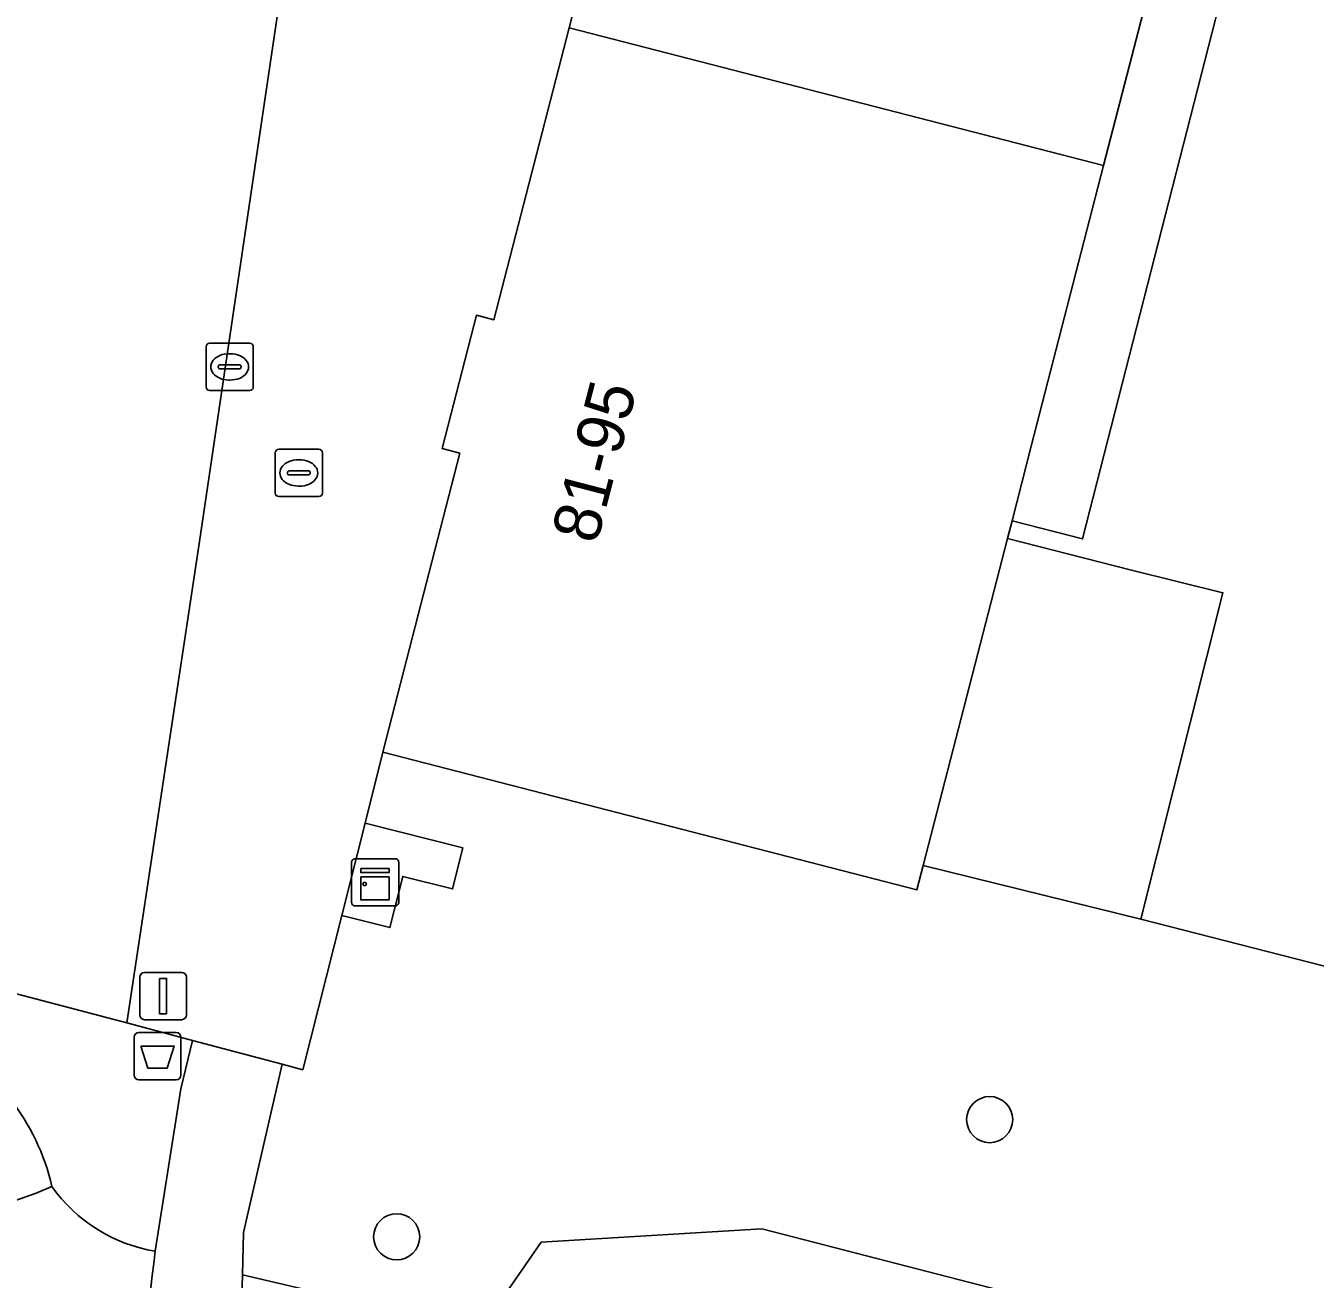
# Model space of a CAD drawing. Extents: x 163683 to 164494, y 382709 to 383872.
# Drawn here: x 164040.92 to 164068.25, y 383122.29 to 383148.85 of the extents above; entities that cross this region are included whole.
import ezdxf

# ---------------------------------------------------------------- set-up
doc = ezdxf.new("R2010")
doc.units = 0
for name, color, linetype in [('IMGEO_Afvalbak', 7, 'Continuous'), ('IMGEO_Boom', 7, 'Continuous'), ('IMGEO_Groenvoorziening', 7, 'Continuous'), ('IMGEO_Kast', 7, 'Continuous'), ('IMGEO_Kolk', 7, 'Continuous'), ('IMGEO_Lichtmast', 7, 'Continuous'), ('IMGEO_Pand', 7, 'Continuous'), ('IMGEO_Pand_nummerreeks', 7, 'Continuous'), ('IMGEO_Rioolput', 7, 'Continuous'), ('IMGEO_Terreindeel_gesloten', 7, 'Continuous'), ('IMGEO_Voetpad_halfverhard', 7, 'Continuous'), ('IMGEO_Voetpad_open', 7, 'Continuous')]:
    doc.layers.add(name, color=color, linetype=linetype)

msp = doc.modelspace()

# ---------------------------------------------------------------- linework, layer by layer
at = {"layer": 'IMGEO_Afvalbak'}
for p, q in [((164043.319, 383127.515), (164044.109, 383127.515)), ((164044.109, 383127.515), (164043.319, 383127.515)), ((164043.219, 383126.615), (164043.219, 383127.415)), ((164043.219, 383127.415), (164043.219, 383126.615)), ((164044.209, 383127.415), (164044.209, 383126.615)), ((164044.209, 383126.615), (164044.209, 383127.415)), ((164044.109, 383126.515), (164043.319, 383126.515)), ((164043.319, 383126.515), (164044.109, 383126.515))]:
    msp.add_line(p, q, dxfattribs=at)
msp.add_lwpolyline([(164043.362, 383127.229), (164044.066, 383127.229), (164043.917, 383126.759), (164043.511, 383126.759), (164043.362, 383127.229)], dxfattribs=at)
for centre, start, end in [((164043.319, 383127.415), 90, 180), ((164043.319, 383127.415), 90, 180), ((164044.109, 383127.415), 0, 90), ((164044.109, 383127.415), 360, 90), ((164043.319, 383126.615), 180, 270), ((164043.319, 383126.615), 180, 270), ((164044.109, 383126.615), 270, 0), ((164044.109, 383126.615), 270, 0)]:
    msp.add_arc(centre, 0.1, start, end, dxfattribs=at)
at = {"layer": 'IMGEO_Boom'}
for centre in [(164061.351, 383125.67), (164048.782, 383123.187)]:
    msp.add_circle(centre, 0.489, dxfattribs=at)
at = {"layer": 'IMGEO_Groenvoorziening'}
for points in [[(164033.039, 383156.561), (164032.775, 383155.553), (164034.669, 383155.046), (164036.178, 383154.914), (164040.121, 383152.198), (164037.77, 383136.602), (164036.683, 383129.392), (164043.063, 383127.721), (164044.6, 383137.924), (164047.39, 383156.736), (164048.093, 383161.745), (164033.321, 383156.926)], [(164043.664, 383122.88), (164044.204, 383126.323), (164044.455, 383127.349), (164043.063, 383127.721), (164036.683, 383129.392), (164026.707, 383132.006), (164026.062, 383132.169), (164024.387, 383128.152), (164023.605, 383126.999)], [(164073.286, 383118.477), (164075.444, 383118.477), (164056.521, 383123.358), (164051.842, 383123.072), (164050.554, 383121.2), (164045.512, 383122.377), (164045.457, 383120.45)]]:
    msp.add_lwpolyline(points, dxfattribs=at)
for points in [[(164090.269, 383148.889), (164070.835, 383153.95), (164070.759, 383160.427), (164070.291, 383160.541), (164069.165, 383160.815), (164067.292, 383153.494), (164063.321, 383137.974), (164061.826, 383138.36), (164061.728, 383137.981), (164064.361, 383137.31), (164066.296, 383136.835), (164064.552, 383129.914), (164086.033, 383124.421)], [(164064.361, 383137.31), (164061.728, 383137.981), (164059.942, 383131.053), (164064.552, 383129.914), (164066.296, 383136.835)], [(164082.061, 383116.77), (164083.693, 383116.349), (164084.602, 383116.796), (164086.033, 383124.421), (164064.552, 383129.914), (164059.942, 383131.053), (164059.809, 383130.537), (164048.491, 383133.455), (164048.111, 383131.953), (164050.186, 383131.429), (164049.966, 383130.557), (164048.91, 383130.825), (164048.636, 383129.74), (164047.617, 383129.998), (164046.79, 383126.726), (164046.355, 383126.842), (164045.537, 383123.279), (164045.512, 383122.377), (164050.554, 383121.2), (164051.842, 383123.072), (164056.521, 383123.358), (164075.444, 383118.477)]]:
    msp.add_lwpolyline(points, close=True, dxfattribs=at)
for centre, radius, start, end in [((164036.803, 383123.163), 4.798, 13.1495, 62.5729), ((164036.803, 383123.163), 4.798, 13.1495, 62.5729), ((164037.987, 383132.129), 8.613, 218.9461, 293.8885), ((164037.987, 383132.129), 8.613, 218.9461, 293.8885), ((164044.217, 383126.192), 3.358, 215.2526, 260.5158), ((164044.217, 383126.192), 3.358, 215.2526, 260.5158), ((164083.855, 383117.788), 40.512, 172.78, 184.5241)]:
    msp.add_arc(centre, radius, start, end, dxfattribs=at)
at = {"layer": 'IMGEO_Kast'}
for p, q in [((164047.826, 383130.274), (164047.826, 383131.115)), ((164047.826, 383131.115), (164047.826, 383130.274)), ((164047.901, 383131.199), (164048.742, 383131.199)), ((164048.742, 383131.199), (164047.901, 383131.199)), ((164048.826, 383131.124), (164048.826, 383130.283)), ((164048.826, 383130.283), (164048.826, 383131.124)), ((164048.751, 383130.199), (164047.91, 383130.199)), ((164047.91, 383130.199), (164048.751, 383130.199))]:
    msp.add_line(p, q, dxfattribs=at)
for points in [[(164048.021, 383130.989), (164048.621, 383130.989), (164048.621, 383130.904), (164048.021, 383130.904), (164048.021, 383130.989)], [(164048.021, 383130.814), (164048.621, 383130.814), (164048.621, 383130.325), (164048.021, 383130.325), (164048.021, 383130.814)]]:
    msp.add_lwpolyline(points, dxfattribs=at)
msp.add_circle((164048.105, 383130.663), 0.0377, dxfattribs=at)
for centre, start, end in [((164047.904, 383131.121), 92.4484, 184.2845), ((164047.904, 383131.121), 92.4484, 184.2845), ((164048.748, 383131.121), 2.4484, 94.2845), ((164048.748, 383131.121), 2.4484, 94.2845), ((164047.904, 383130.277), 182.4484, 274.2845), ((164047.904, 383130.277), 182.4484, 274.2845), ((164048.748, 383130.277), 272.4484, 4.2845), ((164048.748, 383130.277), 272.4484, 4.2845)]:
    msp.add_arc(centre, 0.0779, start, end, dxfattribs=at)
at = {"layer": 'IMGEO_Kolk'}
for p, q in [((164044.742, 383141.195), (164044.742, 383142.047)), ((164044.817, 383142.121), (164045.669, 383142.121)), ((164045.743, 383142.047), (164045.743, 383141.195)), ((164045.23, 383141.901), (164045.255, 383141.901)), ((164045.001, 383141.615), (164045.001, 383141.627)), ((164045.439, 383141.578), (164045.041, 383141.578)), ((164045.044, 383141.664), (164045.442, 383141.664)), ((164045.485, 383141.627), (164045.485, 383141.615)), ((164045.253, 383141.341), (164045.228, 383141.341)), ((164045.669, 383141.121), (164044.817, 383141.121))]:
    msp.add_line(p, q, dxfattribs=at)
for points in [[(164044.742, 383141.195), (164044.742, 383142.047)], [(164044.817, 383142.121), (164045.669, 383142.121)], [(164045.743, 383142.047), (164045.743, 383141.195)], [(164045.669, 383141.121), (164044.817, 383141.121)]]:
    msp.add_lwpolyline(points, dxfattribs=at)
for centre, radius, start, end in [((164044.819, 383142.045), 0.0765, 91.552, 178.448), ((164044.819, 383142.045), 0.0765, 91.552, 178.448), ((164045.667, 383142.045), 0.0765, 1.552, 88.448), ((164045.667, 383142.045), 0.0765, 1.552, 88.448), ((164045.041, 383141.624), 0.0403, 85.8775, 175.7526), ((164045.038, 383141.614), 0.0366, 178.938, 274.7102), ((164045.442, 383141.621), 0.043, 264.8664, 352.4533), ((164045.446, 383141.626), 0.0386, 1.7309, 96.639), ((164044.819, 383141.197), 0.0765, 181.552, 268.448), ((164044.819, 383141.197), 0.0765, 181.552, 268.448), ((164045.667, 383141.197), 0.0765, 271.552, 358.448), ((164045.667, 383141.197), 0.0765, 271.552, 358.448)]:
    msp.add_arc(centre, radius, start, end, dxfattribs=at)
for centre, major_axis, ratio, start_param, end_param in [((164045.229, 383141.621), (-0.387, 0.002), 0.722429, 4.712389, 7.853982), ((164045.254, 383141.621), (-0.39, 0.002), 0.717154, 1.570796, 4.712389)]:
    msp.add_ellipse(centre, major_axis=major_axis, ratio=ratio, start_param=start_param, end_param=end_param, dxfattribs=at)
at = {"layer": 'IMGEO_Lichtmast'}
for p, q in [((164043.336, 383127.887), (164043.336, 383128.687)), ((164043.336, 383128.687), (164043.336, 383127.887)), ((164043.436, 383128.787), (164044.226, 383128.787)), ((164044.226, 383128.787), (164043.436, 383128.787)), ((164044.326, 383128.687), (164044.326, 383127.887)), ((164044.326, 383127.887), (164044.326, 383128.687)), ((164044.226, 383127.787), (164043.436, 383127.787)), ((164043.436, 383127.787), (164044.226, 383127.787))]:
    msp.add_line(p, q, dxfattribs=at)
msp.add_lwpolyline([(164043.756, 383128.662), (164043.906, 383128.662), (164043.906, 383127.912), (164043.756, 383127.912), (164043.756, 383128.662)], dxfattribs=at)
for centre, start, end in [((164043.436, 383128.687), 90, 180), ((164043.436, 383128.687), 90, 180), ((164044.226, 383128.687), 0, 90), ((164044.226, 383128.687), 360, 90), ((164043.436, 383127.887), 180, 270), ((164043.436, 383127.887), 180, 270), ((164044.226, 383127.887), 270, 0), ((164044.226, 383127.887), 270, 0)]:
    msp.add_arc(centre, 0.1, start, end, dxfattribs=at)
at = {"layer": 'IMGEO_Pand'}
for points in [[(164063.767, 383145.888), (164065.301, 383151.838), (164065.83, 383153.889), (164067.707, 383161.169), (164067.745, 383161.318), (164056.432, 383164.235), (164054.779, 383157.822), (164054.398, 383157.921), (164053.65, 383155.021), (164054.015, 383154.927), (164052.438, 383148.809)], [(164062.233, 383139.938), (164063.767, 383145.888), (164052.438, 383148.809), (164050.842, 383142.62), (164050.473, 383142.716), (164049.744, 383139.888), (164050.124, 383139.79), (164049.121, 383135.898), (164048.491, 383133.455), (164059.809, 383130.537), (164059.942, 383131.053), (164061.728, 383137.981), (164061.826, 383138.36)]]:
    msp.add_lwpolyline(points, close=True, dxfattribs=at)
at = {"layer": 'IMGEO_Rioolput'}
for p, q in [((164046.282, 383139.874), (164047.134, 383139.874)), ((164046.207, 383138.948), (164046.207, 383139.8)), ((164046.695, 383139.654), (164046.72, 383139.654)), ((164047.208, 383139.8), (164047.208, 383138.948)), ((164046.466, 383139.368), (164046.466, 383139.38)), ((164046.904, 383139.331), (164046.506, 383139.331)), ((164046.509, 383139.417), (164046.907, 383139.417)), ((164046.95, 383139.38), (164046.95, 383139.368)), ((164046.718, 383139.094), (164046.693, 383139.094)), ((164047.134, 383138.874), (164046.282, 383138.874))]:
    msp.add_line(p, q, dxfattribs=at)
for points in [[(164046.282, 383139.874), (164047.134, 383139.874)], [(164046.207, 383138.948), (164046.207, 383139.8)], [(164047.208, 383139.8), (164047.208, 383138.948)], [(164047.134, 383138.874), (164046.282, 383138.874)]]:
    msp.add_lwpolyline(points, dxfattribs=at)
for centre, radius, start, end in [((164046.284, 383139.798), 0.0765, 91.552, 178.448), ((164046.284, 383139.798), 0.0765, 91.552, 178.448), ((164047.132, 383139.798), 0.0765, 1.552, 88.448), ((164047.132, 383139.798), 0.0765, 1.552, 88.448), ((164046.506, 383139.377), 0.0403, 85.8775, 175.7526), ((164046.503, 383139.367), 0.0366, 178.938, 274.7102), ((164046.907, 383139.374), 0.043, 264.8664, 352.4533), ((164046.911, 383139.379), 0.0386, 1.7309, 96.639), ((164046.284, 383138.95), 0.0765, 181.552, 268.448), ((164046.284, 383138.95), 0.0765, 181.552, 268.448), ((164047.132, 383138.95), 0.0765, 271.552, 358.448), ((164047.132, 383138.95), 0.0765, 271.552, 358.448)]:
    msp.add_arc(centre, radius, start, end, dxfattribs=at)
for centre, major_axis, ratio, start_param, end_param in [((164046.694, 383139.374), (-0.387, 0.002), 0.722429, 4.712389, 7.853982), ((164046.719, 383139.374), (-0.39, 0.002), 0.717154, 1.570796, 4.712389)]:
    msp.add_ellipse(centre, major_axis=major_axis, ratio=ratio, start_param=start_param, end_param=end_param, dxfattribs=at)
at = {"layer": 'IMGEO_Terreindeel_gesloten'}
msp.add_lwpolyline([(164047.617, 383129.998), (164048.636, 383129.74), (164048.91, 383130.825), (164049.966, 383130.557), (164050.186, 383131.429), (164048.111, 383131.953)], close=True, dxfattribs=at)
at = {"layer": 'IMGEO_Voetpad_halfverhard'}
msp.add_lwpolyline([(164045.457, 383120.45), (164045.512, 383122.377), (164045.537, 383123.279), (164046.355, 383126.842), (164044.455, 383127.349), (164044.204, 383126.323), (164043.664, 383122.88)], dxfattribs=at)
msp.add_arc((164083.855, 383117.788), 40.512, 172.78, 184.5241, dxfattribs=at)
at = {"layer": 'IMGEO_Voetpad_open'}
msp.add_lwpolyline([(164047.39, 383156.736), (164044.6, 383137.924), (164043.063, 383127.721), (164044.455, 383127.349), (164046.355, 383126.842), (164046.79, 383126.726), (164047.617, 383129.998), (164048.111, 383131.953), (164048.491, 383133.455), (164049.121, 383135.898), (164050.124, 383139.79), (164049.744, 383139.888), (164050.473, 383142.716), (164050.842, 383142.62), (164052.438, 383148.809), (164054.015, 383154.927)], dxfattribs=at)
msp.add_lwpolyline([(164067.292, 383153.494), (164065.83, 383153.889), (164065.301, 383151.838), (164063.767, 383145.888), (164062.233, 383139.938), (164061.826, 383138.36), (164063.321, 383137.974)], close=True, dxfattribs=at)

# ---------------------------------------------------------------- texts
at = {"layer": 'IMGEO_Pand_nummerreeks'}
msp.add_text('81-95', height=1, rotation=75.4815, dxfattribs=at).set_placement((164053.021, 383137.842))

doc.saveas('drawing.dxf')
